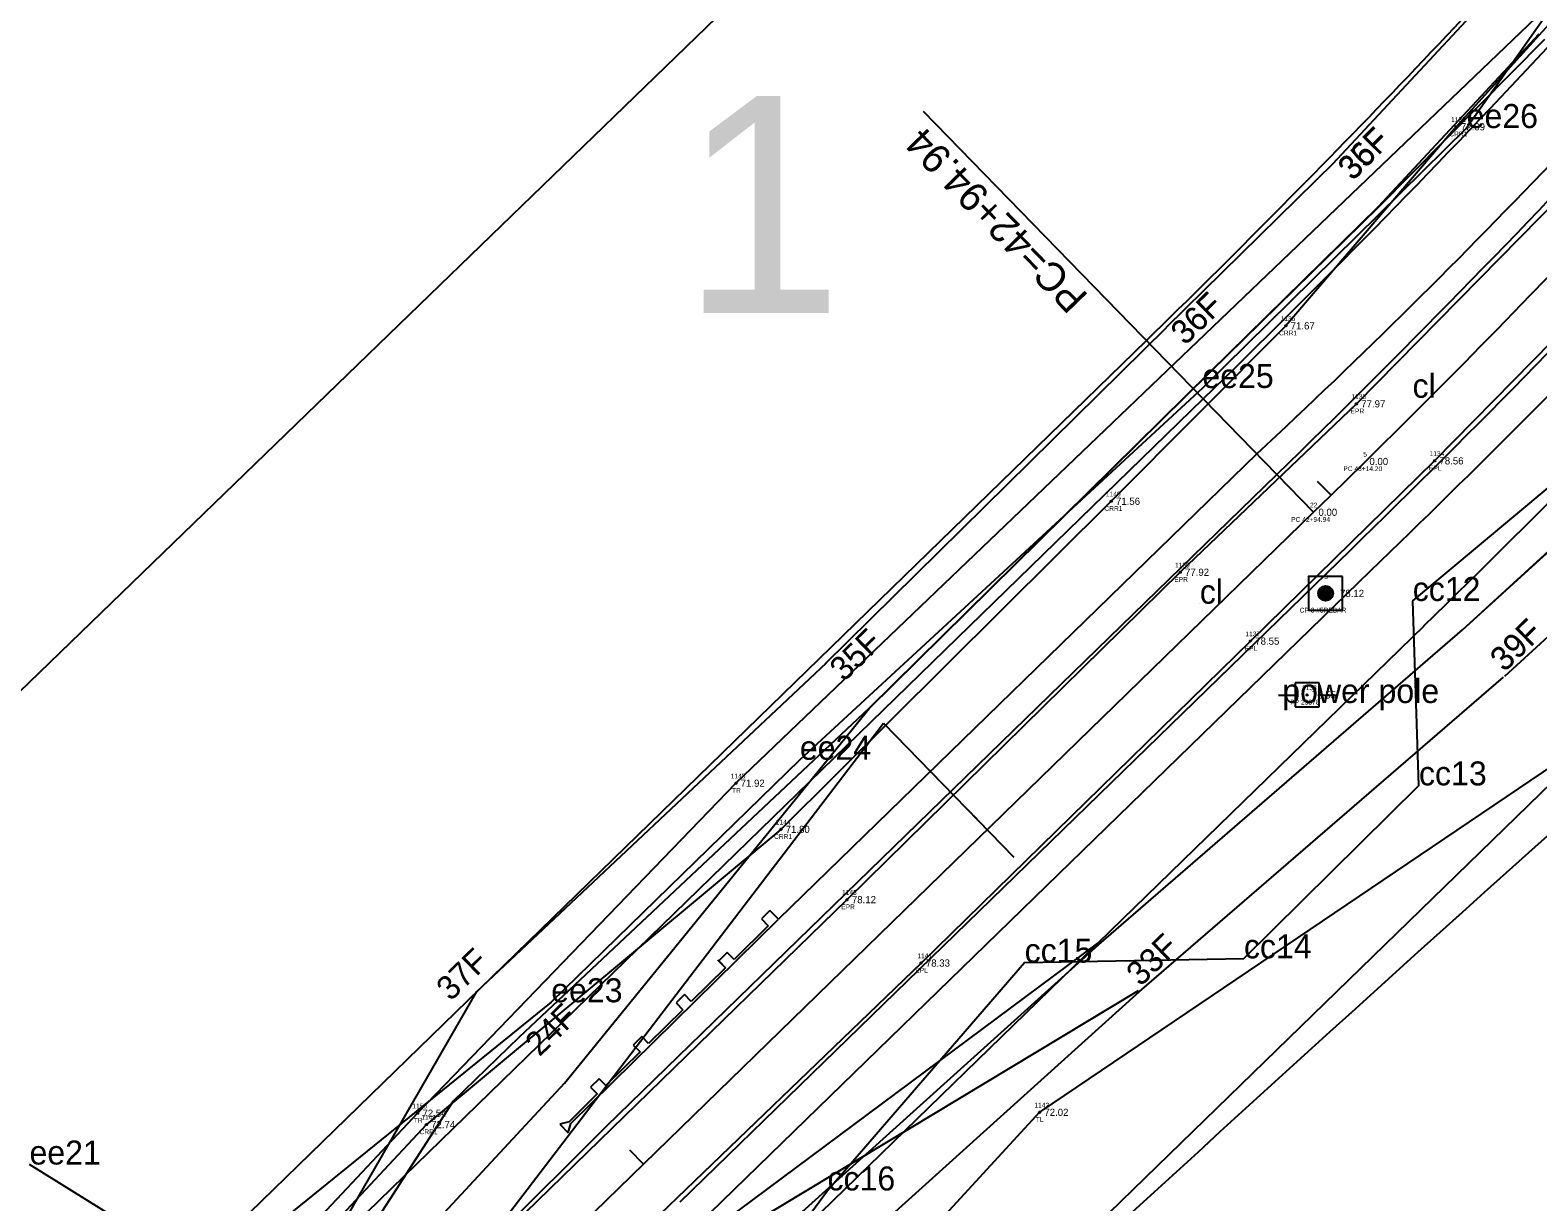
# Model space of a CAD drawing. Extents: x 2500794 to 2511032, y 910653 to 917533.
# Drawn here: x 2505331.2 to 2505645.5, y 913133.7 to 913378 of the extents above; entities that cross this region are included whole.
import ezdxf

# ---------------------------------------------------------------- set-up
doc = ezdxf.new("R2010")
doc.units = 0
for name, color, linetype in [('Default', 7, 'Continuous'), ('RD_EX_DV_TX_Prop', 7, 'Continuous'), ('RD_EX_H2O_txCode', 7, 'Continuous'), ('RD_EX_H2O_WetLd', 7, 'Continuous'), ('RD_EX_Road', 7, 'Continuous'), ('RD_EX_Road_txCode', 7, 'Continuous'), ('RD_EX_RW', 7, 'Continuous'), ('RD_EX_TX_H2O_ELEV', 7, 'Continuous'), ('RD_EX_TX_Road_ELEV', 7, 'Continuous'), ('RD_EX_TX_VEG_ELEV', 7, 'Continuous'), ('RD_EX_UT', 7, 'Continuous'), ('RD_EX_UT_txCode', 7, 'Continuous'), ('RD_EX_VEG', 7, 'Continuous'), ('RD_EX_VEG_txCode', 7, 'Continuous'), ('RD_HC_Cl', 7, 'Continuous'), ('RD_HC_Data', 7, 'Continuous'), ('RD_HC_Data_Tic', 7, 'Continuous'), ('RD_HC_Survey', 7, 'Continuous'), ('RD_HC_Survey_ELEV', 7, 'Continuous'), ('RD_HC_Survey_txCode', 7, 'Continuous'), ('RD_HC_txCode', 7, 'Continuous'), ('RD_PD_ALT1_TrvlWay', 7, 'Continuous'), ('RD_PD_CstnLmt', 7, 'Continuous'), ('RD_PD_CstnLmt_TX', 7, 'Continuous'), ('RD_PD_GR', 7, 'Continuous'), ('RD_PD_RW', 7, 'Continuous'), ('RD_PD_Signals', 7, 'Continuous'), ('RD_Sketch1', 7, 'Continuous'), ('RD_Sketch9', 7, 'Continuous'), ('RD_SMD_Locator', 7, 'Continuous'), ('RD_XS_NPDES', 7, 'Continuous'), ('RD_XS_OSBase', 7, 'Continuous')]:
    doc.layers.add(name, color=color, linetype=linetype)

# ---------------------------------------------------------------- blocks, each defined once
blk = doc.blocks.new('POINT_DISPLAY')
at = {"layer": 'Default'}
blk.add_line((0, 0), (0, 0), dxfattribs=at)
blk = doc.blocks.new('Wetlands')
at = {"layer": 'Default'}
for points in [[(636308.974, 231919.839), (636399.189, 232007.15)], [(636440.916, 232008.067), (636430.194, 231992.837), (636416.2, 231979.068), (636394.884, 231959.377), (636381.718, 231946.531), (636363.719, 231931.947), (636354.09, 231937.935)], [(636348.3, 231893.346), (636354.376, 231887.946), (636372.274, 231903.804), (636390.333, 231923.093), (636391.54, 231930.026), (636396.349, 231936.563), (636406.789, 231948.631), (636418.402, 231948.856), (636427.67, 231958.017), (636427.341, 231967.787), (636436.338, 231975.295), (636454.761, 231993.951), (636472.749, 232019.524)]]:
    blk.add_lwpolyline(points, dxfattribs=at)

msp = doc.modelspace()

# ---------------------------------------------------------------- linework, layer by layer
at = {"layer": 'RD_EX_H2O_txCode'}
msp.add_lwpolyline([(2505789.47, 913464.31), (2505758.18, 913486.1), (2505736.66, 913480.49), (2505719.32, 913463.86), (2505699.9, 913439.21), (2505669.03, 913402.75), (2505628.5, 913357.9), (2505593, 913316.39), (2505556.58, 913279.8), (2505487.72, 913211.38), (2505413.81, 913149.81), (2505341.31, 913072.1)], dxfattribs=at)
at = {"layer": 'RD_EX_Road'}
for points in [[(2505758.23, 913470.96), (2505754.11, 913462.85), (2505725.4, 913427.85), (2505690.77, 913387.11), (2505650.25, 913343.36), (2505607.72, 913300.12), (2505570.97, 913264.99), (2505501.53, 913196.72), (2505431.76, 913128.83), (2505356.25, 913055.37)], [(2505777.56, 913455.88), (2505770.31, 913449.85), (2505741, 913414.45), (2505705.55, 913374.27), (2505664.83, 913329.82), (2505624.02, 913288.23), (2505585.62, 913250.63), (2505516.95, 913183.5), (2505444.27, 913113.56), (2505370.6, 913041.78)]]:
    msp.add_lwpolyline(points, dxfattribs=at)
at = {"layer": 'RD_EX_RW'}
for p, q in [((2505350.02, 913081.57), (2505575.78, 913301.16)), ((2505396.04, 913034.26), (2505621.8, 913253.85))]:
    msp.add_line(p, q, dxfattribs=at)
for radius in [2115.62, 2181.62]:
    msp.add_arc((2504100.66, 914817.69), radius, 314.20692, 319.67523, dxfattribs=at)
at = {"layer": 'RD_EX_UT'}
for p, q in [((2505599.92, 913241.92), (2505594.92, 913241.92)), ((2505594.92, 913241.92), (2505594.92, 913236.92)), ((2505599.92, 913236.92), (2505599.92, 913241.92)), ((2505591.49, 913239.36), (2505594.96, 913239.36)), ((2505594.92, 913236.92), (2505599.92, 913236.92)), ((2505599.85, 913239.36), (2505603.49, 913239.36))]:
    msp.add_line(p, q, dxfattribs=at)
at = {"layer": 'RD_EX_VEG'}
for points in [[(2506002.64, 913815.25), (2505883.7, 913669.64), (2505827.83, 913593.29), (2505814.43, 913589.15), (2505792.49, 913560.55), (2505725.64, 913468.24), (2505664.37, 913399.09), (2505478.33, 913221), (2505411.99, 913152.19), (2505339.13, 913074.53)], [(2505850.96, 913443.27), (2505787.55, 913373.63), (2505723.35, 913275.26), (2505541.65, 913152.37), (2505470.96, 913075.44), (2505402.9, 913005.93)]]:
    msp.add_lwpolyline(points, dxfattribs=at)
at = {"layer": 'RD_HC_Cl'}
msp.add_line((2504540.35, 912247.97), (2505598.79, 913277.5), dxfattribs=at)
msp.add_arc((2504100.66, 914817.69), 2148.62, 314.20692, 322.60071, dxfattribs=at)
at = {"layer": 'RD_HC_Data'}
msp.add_line((2505598.79, 913277.5), (2505517.46, 913361.11), dxfattribs=at)
at = {"layer": 'RD_HC_Data_Tic'}
for p, q in [((2505602.41, 913281.04), (2505599.62, 913283.9)), ((2505530.73, 913211.31), (2505527.94, 913214.17)), ((2505459.05, 913141.58), (2505456.26, 913144.45))]:
    msp.add_line(p, q, dxfattribs=at)
at = {"layer": 'RD_HC_Survey'}
for p, q in [((2505600.22, 913259.46), (2505600.22, 913261.73)), ((2505600.27, 913259.41), (2505600.27, 913261.77)), ((2505600.32, 913259.37), (2505600.32, 913261.81)), ((2505600.37, 913259.33), (2505600.37, 913261.85)), ((2505600.42, 913259.3), (2505600.42, 913261.89)), ((2505600.47, 913259.27), (2505600.47, 913261.92)), ((2505600.52, 913259.24), (2505600.52, 913261.95)), ((2505600.57, 913259.21), (2505600.57, 913261.97)), ((2505600.62, 913259.18), (2505600.62, 913262)), ((2505600.67, 913259.16), (2505600.67, 913262.02)), ((2505600.72, 913259.14), (2505600.72, 913262.04)), ((2505600.77, 913259.12), (2505600.77, 913262.06)), ((2505600.82, 913259.11), (2505600.82, 913262.08)), ((2505600.87, 913259.09), (2505600.87, 913262.09)), ((2505600.92, 913259.08), (2505600.92, 913262.1)), ((2505600.97, 913259.07), (2505600.97, 913262.11)), ((2505601.02, 913259.06), (2505601.02, 913262.12)), ((2505601.07, 913259.05), (2505601.07, 913262.13)), ((2505601.12, 913259.05), (2505601.12, 913262.14)), ((2505601.17, 913259.04), (2505601.17, 913262.14)), ((2505601.22, 913259.04), (2505601.22, 913262.14)), ((2505601.27, 913259.04), (2505601.27, 913262.15)), ((2505601.32, 913259.04), (2505601.32, 913262.15)), ((2505601.37, 913259.04), (2505601.37, 913262.14)), ((2505601.42, 913259.04), (2505601.42, 913262.14)), ((2505601.47, 913259.05), (2505601.47, 913262.13)), ((2505601.52, 913259.06), (2505601.52, 913262.13)), ((2505601.57, 913259.06), (2505601.57, 913262.12)), ((2505601.62, 913259.07), (2505601.62, 913262.11)), ((2505601.67, 913259.09), (2505601.67, 913262.1)), ((2505601.72, 913259.1), (2505601.72, 913262.08)), ((2505601.77, 913259.12), (2505601.77, 913262.07)), ((2505601.82, 913259.13), (2505601.82, 913262.05)), ((2505601.87, 913259.15), (2505601.87, 913262.03)), ((2505601.92, 913259.17), (2505601.92, 913262.01)), ((2505601.97, 913259.2), (2505601.97, 913261.99)), ((2505602.02, 913259.22), (2505602.02, 913261.96)), ((2505602.07, 913259.25), (2505602.07, 913261.93)), ((2505602.12, 913259.28), (2505602.12, 913261.9)), ((2505602.17, 913259.32), (2505602.17, 913261.87)), ((2505602.22, 913259.35), (2505602.22, 913261.83)), ((2505602.27, 913259.39), (2505602.27, 913261.79)), ((2505602.32, 913259.43), (2505602.32, 913261.75)), ((2505602.37, 913259.48), (2505602.37, 913261.7)), ((2505599.77, 913260.23), (2505599.77, 913260.95)), ((2505599.82, 913260.06), (2505599.82, 913261.12)), ((2505599.87, 913259.94), (2505599.87, 913261.24)), ((2505599.92, 913259.84), (2505599.92, 913261.34)), ((2505599.97, 913259.76), (2505599.97, 913261.43)), ((2505600.02, 913259.68), (2505600.02, 913261.5)), ((2505600.07, 913259.62), (2505600.07, 913261.57)), ((2505600.12, 913259.56), (2505600.12, 913261.62)), ((2505600.17, 913259.51), (2505600.17, 913261.68)), ((2505602.42, 913259.53), (2505602.42, 913261.65)), ((2505602.47, 913259.59), (2505602.47, 913261.59)), ((2505602.52, 913259.65), (2505602.52, 913261.53)), ((2505602.57, 913259.72), (2505602.57, 913261.46)), ((2505602.62, 913259.8), (2505602.62, 913261.38)), ((2505602.67, 913259.89), (2505602.67, 913261.29)), ((2505602.72, 913260), (2505602.72, 913261.18)), ((2505602.77, 913260.14), (2505602.77, 913261.04)), ((2505602.82, 913260.37), (2505602.82, 913260.82))]:
    msp.add_line(p, q, dxfattribs=at)
msp.add_lwpolyline([(2505604.82, 913264.13), (2505597.75, 913264.13), (2505597.75, 913257.06), (2505604.82, 913257.06)], close=True, dxfattribs=at)
msp.add_circle((2505601.29, 913260.59), 1.55, dxfattribs=at)
at = {"layer": 'RD_PD_ALT1_TrvlWay'}
for p, q in [((2505451.38, 913149.47), (2505591.12, 913285.39)), ((2505466.72, 913133.7), (2505606.46, 913269.62)), ((2505451.38, 913149.47), (2505380.48, 913078.94))]:
    msp.add_line(p, q, dxfattribs=at)
for radius, end in [(2137.62, 319.99941), (2159.62, 320.00487)]:
    msp.add_arc((2504100.66, 914817.69), radius, 314.20692, end, dxfattribs=at)
at = {"layer": 'RD_PD_CstnLmt'}
for p, q in [((2505612.28, 913341.28), (2505645.8, 913377.25)), ((2505577.22, 913306.81), (2505612.28, 913341.28)), ((2505506.11, 913236.62), (2505577.22, 913306.81)), ((2505629.85, 913252.96), (2505667.51, 913287.34)), ((2505554, 913187.39), (2505629.85, 913252.96)), ((2505433.25, 913168.1), (2505506.11, 913236.62)), ((2505479.68, 913120.37), (2505554, 913187.39)), ((2505419.5, 913154.73), (2505433.25, 913168.1)), ((2505374.45, 913085.13), (2505419.5, 913154.73))]:
    msp.add_line(p, q, dxfattribs=at)
at = {"layer": 'RD_PD_GR'}
for p, q in [((2505586.93, 913289.69), (2505487.21, 913192.68)), ((2505406.21, 913066.47), (2505610.64, 913265.32)), ((2505443.91, 913150.05), (2505487.21, 913192.68)), ((2505485.45, 913194.47), (2505483.67, 913192.71)), ((2505483.67, 913192.71), (2505485.08, 913191.28)), ((2505487.21, 913192.68), (2505485.45, 913194.47)), ((2505485.08, 913191.28), (2505477.95, 913184.27)), ((2505474.54, 913184.17), (2505475.95, 913182.74)), ((2505476.55, 913185.7), (2505474.76, 913183.94)), ((2505474.76, 913183.94), (2505476.17, 913182.51)), ((2505477.95, 913184.27), (2505476.55, 913185.7)), ((2505476.17, 913182.51), (2505469.05, 913175.49)), ((2505467.64, 913176.93), (2505465.86, 913175.17)), ((2505469.05, 913175.49), (2505467.64, 913176.93)), ((2505467.27, 913173.74), (2505460.14, 913166.72)), ((2505465.86, 913175.17), (2505467.27, 913173.74)), ((2505458.73, 913168.16), (2505456.95, 913166.4)), ((2505460.14, 913166.72), (2505458.73, 913168.16)), ((2505458.36, 913164.97), (2505451.23, 913157.95)), ((2505456.95, 913166.4), (2505458.36, 913164.97)), ((2505449.83, 913159.38), (2505448.04, 913157.63)), ((2505451.23, 913157.95), (2505449.83, 913159.38)), ((2505449.45, 913156.2), (2505443.56, 913150.4)), ((2505448.04, 913157.63), (2505449.45, 913156.2)), ((2505443.56, 913150.4), (2505441.63, 913149.9)), ((2505441.63, 913149.9), (2505443.37, 913148.12)), ((2505443.37, 913148.12), (2505443.91, 913150.05))]:
    msp.add_line(p, q, dxfattribs=at)
for centre, radius, start, end in [((2504614.7, 914336.04), 1428.32, 312.89707, 320.06268), ((2504296.24, 914635.52), 1898.71, 313.80927, 319.3112)]:
    msp.add_arc(centre, radius, start, end, dxfattribs=at)
at = {"layer": 'RD_PD_RW'}
for p, q in [((2505338.17, 913093.75), (2505563.92, 913313.34)), ((2505425.33, 913004.15), (2505651.08, 913223.74))]:
    msp.add_line(p, q, dxfattribs=at)
msp.add_arc((2504100.66, 914817.69), 2098.62, 314.20692, 318.31015, dxfattribs=at)
at = {"layer": 'RD_PD_Signals'}
for p, q in [((2505612.37, 913341.2), (2505646.99, 913376.15)), ((2505577.26, 913306.77), (2505612.37, 913341.2)), ((2505506.12, 913236.61), (2505577.26, 913306.77)), ((2505629.82, 913253), (2505667.43, 913287.42)), ((2505553.99, 913187.4), (2505629.82, 913253)), ((2505442.63, 913158.47), (2505506.12, 913236.61)), ((2505479.68, 913120.37), (2505553.99, 913187.4)), ((2505374.49, 913085.09), (2505442.63, 913158.47))]:
    msp.add_line(p, q, dxfattribs=at)
at = {"layer": 'RD_Sketch1'}
for p, q in [((2505380.2, 913064.88), (2505509.12, 913233.53)), ((2505509.12, 913233.53), (2505536.31, 913205.57))]:
    msp.add_line(p, q, dxfattribs=at)
at = {"layer": 'RD_Sketch9'}
msp.add_arc((2511264.32, 906930.5), 8425, 131.510647, 134.206919, dxfattribs=at)
at = {"layer": 'RD_SMD_Locator'}
for centre in [(2505628.5, 913357.9), (2505593, 913316.39), (2505607.72, 913300.12), (2505624.02, 913288.23), (2505556.58, 913279.8), (2505570.97, 913264.99), (2505601.29, 913260.59), (2505585.62, 913250.63), (2505597.43, 913239.41), (2505478.33, 913221), (2505487.72, 913211.38), (2505501.53, 913196.72), (2505516.95, 913183.5), (2505411.99, 913152.19), (2505541.65, 913152.37), (2505413.81, 913149.81)]:
    msp.add_circle(centre, 0.15, dxfattribs=at)
at = {"layer": 'RD_XS_NPDES'}
for p, q in [((2505602.77, 913350.15), (2505636.29, 913386.12)), ((2505568.11, 913316.08), (2505603.16, 913350.55)), ((2505496.98, 913245.88), (2505568.09, 913316.07)), ((2505638.62, 913243.36), (2505676.28, 913277.74)), ((2505424.35, 913177.57), (2505497.2, 913246.09)), ((2505562.5, 913177.55), (2505638.36, 913243.12)), ((2505371.93, 913086.77), (2505424.35, 913177.57)), ((2505488.97, 913111.28), (2505562.5, 913177.55))]:
    msp.add_line(p, q, dxfattribs=at)
at = {"layer": 'RD_XS_OSBase'}
for p, q in [((2505472.87, 913127.38), (2505553.78, 913187.61)), ((2505474.8, 913125.07), (2505562.29, 913177.78))]:
    msp.add_line(p, q, dxfattribs=at)

# ---------------------------------------------------------------- block references
at = {"layer": 'Default', "xscale": 3.937007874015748, "yscale": 3.937007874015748}
for name, p in [('Wetlands', (0, 0)), ('POINT_DISPLAY', (2505630.69, 913357.63)), ('POINT_DISPLAY', (2505630.69, 913357.63)), ('POINT_DISPLAY', (2505575.59, 913303.42)), ('POINT_DISPLAY', (2505575.59, 913303.42)), ('POINT_DISPLAY', (2505619.4, 913301.38)), ('POINT_DISPLAY', (2505619.4, 913301.38)), ('POINT_DISPLAY', (2505619.45, 913259)), ('POINT_DISPLAY', (2505619.45, 913259)), ('POINT_DISPLAY', (2505575.06, 913258.43)), ('POINT_DISPLAY', (2505575.06, 913258.43)), ('POINT_DISPLAY', (2505592.25, 913237.73)), ('POINT_DISPLAY', (2505592.25, 913237.73)), ('POINT_DISPLAY', (2505491.67, 913225.89)), ('POINT_DISPLAY', (2505491.67, 913225.89)), ('POINT_DISPLAY', (2505620.75, 913220.54)), ('POINT_DISPLAY', (2505620.75, 913220.54)), ('POINT_DISPLAY', (2505538.54, 913183.59)), ('POINT_DISPLAY', (2505538.54, 913183.59)), ('POINT_DISPLAY', (2505584.26, 913184.47)), ('POINT_DISPLAY', (2505584.26, 913184.47)), ('POINT_DISPLAY', (2505439.84, 913175.32)), ('POINT_DISPLAY', (2505439.84, 913175.32)), ('POINT_DISPLAY', (2505497.44, 913136.07)), ('POINT_DISPLAY', (2505497.44, 913136.07))]:
    msp.add_blockref(name, p, dxfattribs=at)
at = {"layer": 'RD_EX_H2O_WetLd', "xscale": 3.937007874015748, "yscale": 3.937007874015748}
msp.add_blockref('Wetlands', (0, 0), dxfattribs=at)

# ---------------------------------------------------------------- texts
at = {"layer": 'Default'}
for s, p in [('ee26', (2505630.69, 913357.63)), ('ee26', (2505630.69, 913357.63)), ('ee25', (2505575.59, 913303.42)), ('ee25', (2505575.59, 913303.42)), ('cl', (2505619.4, 913301.38)), ('cl', (2505619.4, 913301.38)), ('cl', (2505575.06, 913258.43)), ('cl', (2505575.06, 913258.43)), ('cc12', (2505619.45, 913259)), ('cc12', (2505619.45, 913259)), ('power pole', (2505592.25, 913237.73)), ('power pole', (2505592.25, 913237.73)), ('ee24', (2505491.67, 913225.89)), ('ee24', (2505491.67, 913225.89)), ('cc13', (2505620.75, 913220.54)), ('cc13', (2505620.75, 913220.54)), ('cc14', (2505584.26, 913184.47)), ('cc14', (2505584.26, 913184.47)), ('cc15', (2505538.54, 913183.59)), ('cc15', (2505538.54, 913183.59)), ('ee23', (2505439.84, 913175.32)), ('ee23', (2505439.84, 913175.32)), ('ee21', (2505331.07, 913141.48)), ('ee21', (2505331.07, 913141.48)), ('cc16', (2505497.44, 913136.07)), ('cc16', (2505497.44, 913136.07))]:
    msp.add_text(s, height=5, dxfattribs=at).set_placement(p)
at = {"layer": 'RD_EX_DV_TX_Prop'}
msp.add_text('1', height=45.26, dxfattribs=at).set_placement((2505467.01, 913319.03))
at = {"layer": 'RD_EX_H2O_txCode'}
for s, p in [('1133', (2505627.44, 913358.9)), ('CRR1', (2505627.09, 913355.9)), ('1136', (2505591.91, 913317.39)), ('CRR1', (2505591.58, 913314.39)), ('1140', (2505555.48, 913280.8)), ('CRR1', (2505555.17, 913277.8)), ('1144', (2505486.66, 913212.38)), ('CRR1', (2505486.31, 913209.38)), ('1149', (2505412.75, 913150.81)), ('CRR1', (2505412.39, 913147.81))]:
    msp.add_text(s, height=1, dxfattribs=at).set_placement(p)
at = {"layer": 'RD_EX_Road_txCode'}
for s, p in [('1135', (2505606.66, 913301.12)), ('EPR', (2505606.49, 913298.12)), ('1134', (2505622.96, 913289.23)), ('EPL', (2505622.82, 913286.23)), ('1139', (2505569.9, 913265.99)), ('EPR', (2505569.74, 913262.99)), ('1137', (2505584.56, 913251.63)), ('EPL', (2505584.42, 913248.63)), ('EPR', (2505500.3, 913194.72)), ('1143', (2505500.47, 913197.72)), ('1141', (2505516.17, 913184.5)), ('EPL', (2505515.75, 913181.5))]:
    msp.add_text(s, height=1, dxfattribs=at).set_placement(p)
at = {"layer": 'RD_EX_TX_H2O_ELEV'}
for s, p in [('72.09', (2505629.5, 913357.15)), ('71.67', (2505594, 913315.64)), ('71.56', (2505557.58, 913279.05)), ('71.80', (2505488.72, 913210.63)), ('72.74', (2505414.81, 913149.06))]:
    msp.add_text(s, height=1.5, dxfattribs=at).set_placement(p)
at = {"layer": 'RD_EX_TX_Road_ELEV'}
for s, p in [('77.97', (2505608.72, 913299.37)), ('78.56', (2505625.02, 913287.48)), ('77.92', (2505571.97, 913264.24)), ('78.55', (2505586.62, 913249.88)), ('78.12', (2505502.53, 913195.97)), ('78.33', (2505517.95, 913182.75))]:
    msp.add_text(s, height=1.5, dxfattribs=at).set_placement(p)
at = {"layer": 'RD_EX_TX_VEG_ELEV'}
for s, p in [('71.92', (2505479.33, 913220.25)), ('72.54', (2505412.99, 913151.44)), ('72.02', (2505542.65, 913151.62))]:
    msp.add_text(s, height=1.5, dxfattribs=at).set_placement(p)
at = {"layer": 'RD_EX_UT_txCode'}
for s, p in [('1138', (2505596.37, 913240.41)), ('PP 23378', (2505593.93, 913237.41))]:
    msp.add_text(s, height=1, dxfattribs=at).set_placement(p)
at = {"layer": 'RD_EX_VEG_txCode'}
for s, p in [('1145', (2505477.27, 913222)), ('TR', (2505477.53, 913219)), ('1150', (2505410.88, 913153.19)), ('1142', (2505540.58, 913153.37)), ('TR', (2505411.19, 913150.19)), ('TL', (2505540.87, 913150.37))]:
    msp.add_text(s, height=1, dxfattribs=at).set_placement(p)
at = {"layer": 'RD_HC_Data'}
msp.add_text('PC=42+94.94', height=6, rotation=134.2069, dxfattribs=at).set_placement((2505552.03, 913322.7))
at = {"layer": 'RD_HC_Survey_ELEV'}
for s, p in [('0.00', (2505610.42, 913287.35)), ('0.00', (2505599.79, 913276.75)), ('78.12', (2505604.29, 913259.84)), ('76.55', (2505598.43, 913238.66))]:
    msp.add_text(s, height=1.5, dxfattribs=at).set_placement(p)
at = {"layer": 'RD_HC_Survey_txCode'}
for s, p in [('3', (2505601, 913263.59)), ('CP 3 #5REBAR', (2505595.88, 913256.59))]:
    msp.add_text(s, height=1, dxfattribs=at).set_placement(p)
at = {"layer": 'RD_HC_txCode'}
for s, p in [('5', (2505609.14, 913289.1)), ('PC 43+14.20', (2505604.99, 913286.1)), ('22', (2505598.05, 913278.5)), ('PC 42+94.94', (2505594.11, 913275.5))]:
    msp.add_text(s, height=1, dxfattribs=at).set_placement(p)
at = {"layer": 'RD_PD_CstnLmt_TX'}
for s, rotation, p in [('36F', 45.6753, (2505606.91, 913346.53)), ('36F', 44.342, (2505571.98, 913312.18)), ('39F', 44.342, (2505638.59, 913244.02)), ('35F', 44.2069, (2505500.88, 913242)), ('33F', 44.2069, (2505562.72, 913178.43)), ('37F', 44.2069, (2505418.87, 913175.38))]:
    msp.add_text(s, height=5, rotation=rotation, dxfattribs=at).set_placement(p)
at = {"layer": 'RD_PD_Signals'}
for s, rotation, p in [('35F', 45.6753, (2505607, 913346.44)), ('36F', 44.342, (2505572.02, 913312.14)), ('39F', 44.342, (2505638.55, 913244.06)), ('35F', 44.2069, (2505500.89, 913241.99)), ('33F', 44.2069, (2505562.71, 913178.44)), ('24F', 44.2069, (2505437.4, 913163.84))]:
    msp.add_text(s, height=5, rotation=rotation, dxfattribs=at).set_placement(p)

doc.saveas('drawing.dxf')
